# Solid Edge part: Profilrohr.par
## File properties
Dokumentum tartalom típus: 0
Last saved by: bmolnar
Revision: 76
Sűrűség: 0,000 kg/m^3
Pontosság: 0,990
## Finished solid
Body 1: solid body, 95 faces, 278 edges, 184 vertices.
  Faces by surface: plane 48, cylinder 47
  Edges by curve: line 184, circle 94
Bounding box of the edges (mm): 65.500 x 65.500 x 21.000, from (-32.75, -32.75, 0) to (32.75, 32.75, 21).
Cylindrical faces by radius (mm): R0.15 x20, R0.25 x20, R6.5 x2, R8 x4, R25 x1
Planar faces by outward normal: +x 11, +y 12, +z 1, -x 11, -y 12, -z 1
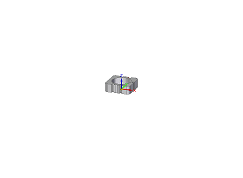
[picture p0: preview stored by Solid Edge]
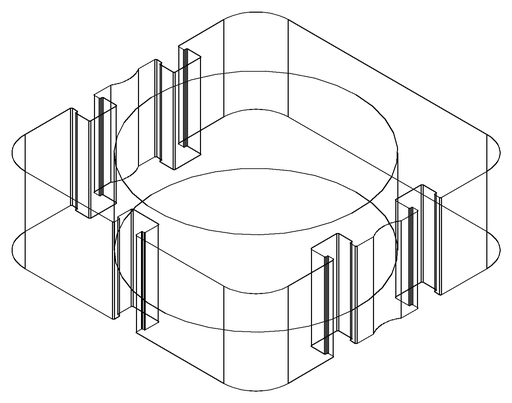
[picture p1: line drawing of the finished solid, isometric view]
